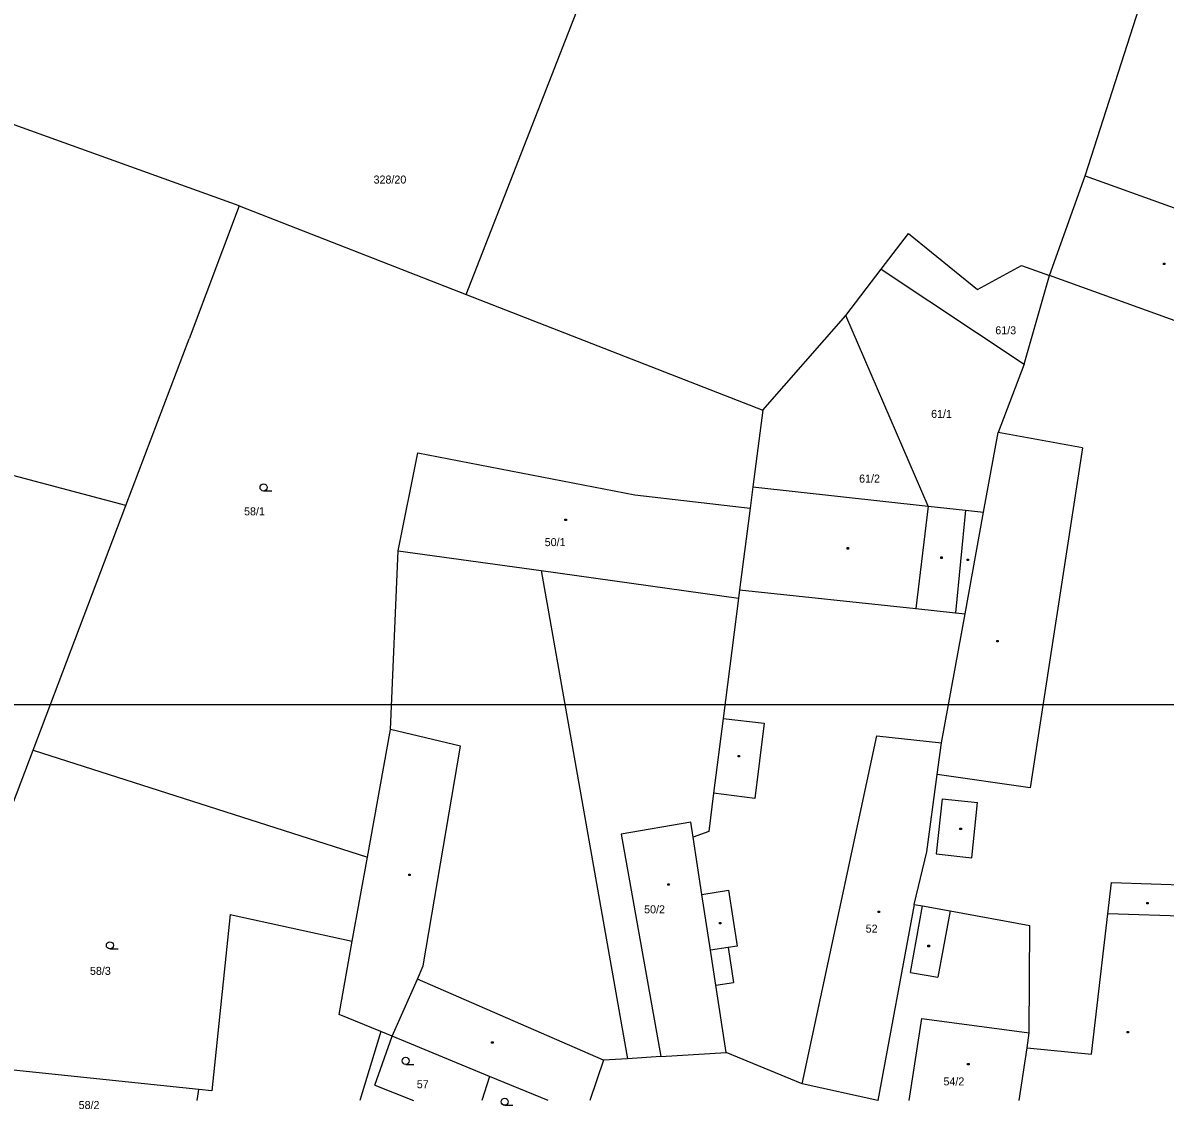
# Model space of a CAD drawing. Extents: x -770973 to -770265, y -1049936 to -1049427.
# Drawn here: x -770758.9 to -770637.6, y -1049935.7 to -1049820.3 of the extents above; entities that cross this region are included whole.
import ezdxf

# ---------------------------------------------------------------- set-up
doc = ezdxf.new("R2010")
doc.units = 0
for name, color, linetype in [('Vrstva 1', 7, 'Continuous'), ('Vrstva 14', 7, 'Continuous'), ('Vrstva 15', 7, 'Continuous'), ('Vrstva 2', 7, 'Continuous'), ('Vrstva 23', 7, 'Continuous'), ('Vrstva 25', 7, 'Continuous'), ('Vrstva 63', 7, 'Continuous')]:
    doc.layers.add(name, color=color, linetype=linetype)

msp = doc.modelspace()

# ---------------------------------------------------------------- linework, layer by layer
at = {"layer": 'Vrstva 1'}
for p, q in [((-770646.07, -1049836.54), (-770633.83, -1049798.35)), ((-770711.83, -1049849.13), (-770698.8, -1049815.74)), ((-770735.94, -1049839.73), (-770785.94, -1049821.72)), ((-770649.88, -1049847.14), (-770646.07, -1049836.54)), ((-770646.07, -1049836.54), (-770626.01, -1049843.75)), ((-770735.94, -1049839.73), (-770741.27, -1049853.85)), ((-770735.94, -1049839.73), (-770711.83, -1049849.13)), ((-770667.76, -1049846.45), (-770664.86, -1049842.66)), ((-770664.86, -1049842.66), (-770657.53, -1049848.62)), ((-770671.51, -1049851.36), (-770667.76, -1049846.45)), ((-770667.76, -1049846.45), (-770652.56, -1049856.54)), ((-770657.53, -1049848.62), (-770652.84, -1049846.08)), ((-770652.84, -1049846.08), (-770649.88, -1049847.14)), ((-770652.56, -1049856.54), (-770649.88, -1049847.14)), ((-770711.83, -1049849.13), (-770680.33, -1049861.42)), ((-770680.33, -1049861.42), (-770671.51, -1049851.36)), ((-770662.74, -1049871.61), (-770671.51, -1049851.36)), ((-770747.99, -1049871.56), (-770741.27, -1049853.85)), ((-770652.56, -1049856.54), (-770655.31, -1049863.79)), ((-770747.99, -1049871.56), (-770799.97, -1049857.75)), ((-770680.33, -1049861.42), (-770681.37, -1049869.56)), ((-770656.86, -1049872.26), (-770655.31, -1049863.79)), ((-770719.06, -1049876.36), (-770716.96, -1049865.96)), ((-770716.96, -1049865.96), (-770693.91, -1049870.43)), ((-770681.37, -1049869.56), (-770681.66, -1049871.83)), ((-770681.37, -1049869.56), (-770662.74, -1049871.61)), ((-770693.91, -1049870.43), (-770681.66, -1049871.83)), ((-770757.85, -1049897.54), (-770747.99, -1049871.56)), ((-770681.66, -1049871.83), (-770682.78, -1049880.53)), ((-770662.74, -1049871.61), (-770658.78, -1049872.05)), ((-770658.83, -1049883.07), (-770656.86, -1049872.26)), ((-770658.78, -1049872.05), (-770656.86, -1049872.26)), ((-770719.89, -1049895.36), (-770719.06, -1049876.36)), ((-770703.85, -1049878.47), (-770694.68, -1049930.32)), ((-770703.85, -1049878.47), (-770682.89, -1049881.38)), ((-770682.78, -1049880.53), (-770682.89, -1049881.38)), ((-770682.89, -1049881.38), (-770684.53, -1049894.18)), ((-770661.33, -1049896.78), (-770658.83, -1049883.07)), ((-770684.53, -1049894.18), (-770685.55, -1049902.12)), ((-770722.33, -1049908.91), (-770719.89, -1049895.36)), ((-770661.79, -1049900.14), (-770661.33, -1049896.78)), ((-770760.01, -1049903.23), (-770757.85, -1049897.54)), ((-770757.85, -1049897.54), (-770722.33, -1049908.91)), ((-770662.9, -1049908.35), (-770661.79, -1049900.14)), ((-770685.55, -1049902.12), (-770686.07, -1049906.19)), ((-770686.07, -1049906.19), (-770687.73, -1049906.77)), ((-770686.79, -1049912.86), (-770687.73, -1049906.77)), ((-770723.94, -1049917.84), (-770722.33, -1049908.91)), ((-770664.25, -1049913.92), (-770662.9, -1049908.35)), ((-770685.88, -1049918.79), (-770686.79, -1049912.86)), ((-770736.91, -1049915), (-770738.87, -1049933.74)), ((-770736.91, -1049915), (-770723.94, -1049917.84)), ((-770664.25, -1049913.92), (-770668.1, -1049934.74)), ((-770664.25, -1049913.92), (-770663.34, -1049914.09)), ((-770663.34, -1049914.09), (-770660.43, -1049914.62)), ((-770660.43, -1049914.62), (-770651.97, -1049916.16)), ((-770652.01, -1049927.55), (-770651.97, -1049916.16)), ((-770725.34, -1049925.61), (-770723.94, -1049917.84)), ((-770685.31, -1049922.52), (-770685.88, -1049918.79)), ((-770684.21, -1049929.65), (-770685.31, -1049922.52)), ((-770720.91, -1049927.44), (-770725.34, -1049925.61)), ((-770720.91, -1049927.44), (-770723.14, -1049934.76)), ((-770721.53, -1049933.14), (-770719.71, -1049927.93)), ((-770719.71, -1049927.93), (-770720.91, -1049927.44)), ((-770709.37, -1049932.19), (-770719.71, -1049927.93)), ((-770652.25, -1049929.16), (-770652.01, -1049927.55)), ((-770653.07, -1049934.76), (-770652.25, -1049929.16)), ((-770740.24, -1049933.6), (-770769.85, -1049930.5)), ((-770697.24, -1049930.48), (-770698.7, -1049934.76)), ((-770694.68, -1049930.32), (-770697.24, -1049930.48)), ((-770691.14, -1049930.09), (-770694.68, -1049930.32)), ((-770691.14, -1049930.09), (-770684.21, -1049929.65)), ((-770676.15, -1049932.97), (-770684.21, -1049929.65)), ((-770721.53, -1049933.14), (-770717.42, -1049934.76)), ((-770709.37, -1049932.19), (-770710.18, -1049934.76)), ((-770703.13, -1049934.76), (-770709.37, -1049932.19)), ((-770668.1, -1049934.74), (-770676.15, -1049932.97)), ((-770740.41, -1049934.76), (-770740.24, -1049933.6)), ((-770738.87, -1049933.74), (-770740.24, -1049933.6)), ((-770668.07, -1049934.76), (-770668.1, -1049934.74))]:
    msp.add_line(p, q, dxfattribs=at)
at = {"layer": 'Vrstva 2'}
for p, q in [((-770630.25, -1049854.2), (-770649.88, -1049847.14)), ((-770646.35, -1049865.43), (-770655.31, -1049863.79)), ((-770646.35, -1049865.43), (-770651.91, -1049901.53)), ((-770662.74, -1049871.61), (-770664.06, -1049882.51)), ((-770658.78, -1049872.05), (-770659.86, -1049882.96)), ((-770719.06, -1049876.36), (-770703.85, -1049878.47)), ((-770682.78, -1049880.53), (-770664.06, -1049882.51)), ((-770664.06, -1049882.51), (-770659.86, -1049882.96)), ((-770659.86, -1049882.96), (-770658.83, -1049883.07)), ((-770684.53, -1049894.18), (-770680.16, -1049894.67)), ((-770712.42, -1049897.11), (-770719.89, -1049895.36)), ((-770680.16, -1049894.67), (-770681.18, -1049902.68)), ((-770676.15, -1049932.97), (-770668.2, -1049896.01)), ((-770668.2, -1049896.01), (-770661.33, -1049896.78)), ((-770716.39, -1049920.44), (-770712.42, -1049897.11)), ((-770651.91, -1049901.53), (-770661.79, -1049900.14)), ((-770681.18, -1049902.68), (-770685.55, -1049902.12)), ((-770661.28, -1049902.71), (-770661.89, -1049908.57)), ((-770661.28, -1049902.71), (-770657.5, -1049903.11)), ((-770658.11, -1049908.97), (-770657.5, -1049903.11)), ((-770687.97, -1049905.19), (-770695.36, -1049906.47)), ((-770687.73, -1049906.77), (-770687.97, -1049905.19)), ((-770695.36, -1049906.47), (-770691.14, -1049930.09)), ((-770661.89, -1049908.57), (-770658.11, -1049908.97)), ((-770686.79, -1049912.86), (-770683.95, -1049912.42)), ((-770683.95, -1049912.42), (-770683.04, -1049918.35)), ((-770643.67, -1049914.92), (-770643.29, -1049911.61)), ((-770643.29, -1049911.61), (-770634.44, -1049911.9)), ((-770664.62, -1049921.14), (-770663.34, -1049914.09)), ((-770660.43, -1049914.62), (-770661.71, -1049921.67)), ((-770645.39, -1049929.82), (-770643.67, -1049914.92)), ((-770634.76, -1049915.2), (-770643.67, -1049914.92)), ((-770684, -1049918.5), (-770685.88, -1049918.79)), ((-770683.04, -1049918.35), (-770684, -1049918.5)), ((-770684, -1049918.5), (-770683.42, -1049922.23)), ((-770717.02, -1049921.86), (-770716.39, -1049920.44)), ((-770719.71, -1049927.93), (-770717.02, -1049921.86)), ((-770697.24, -1049930.48), (-770717.02, -1049921.86)), ((-770685.31, -1049922.52), (-770683.42, -1049922.23)), ((-770664.62, -1049921.14), (-770661.71, -1049921.67)), ((-770664.76, -1049934.76), (-770663.42, -1049926.03)), ((-770663.42, -1049926.03), (-770652.01, -1049927.55)), ((-770652.25, -1049929.16), (-770645.39, -1049929.82))]:
    msp.add_line(p, q, dxfattribs=at)
at = {"layer": 'Vrstva 23'}
for p, q in [((-770733.36, -1049870.01), (-770732.48, -1049870.01)), ((-770749.68, -1049918.65), (-770748.8, -1049918.65)), ((-770718.26, -1049930.92), (-770717.38, -1049930.92)), ((-770707.74, -1049935.26), (-770706.86, -1049935.26))]:
    msp.add_line(p, q, dxfattribs=at)
for centre in [(-770733.36, -1049869.64), (-770749.68, -1049918.27), (-770718.26, -1049930.54), (-770707.74, -1049934.89)]:
    msp.add_circle(centre, 0.375, dxfattribs=at)
at = {"layer": 'Vrstva 25'}
for p, q in [((-770637.77, -1049845.81), (-770637.62, -1049845.81)), ((-770637.77, -1049845.96), (-770637.77, -1049845.81)), ((-770637.62, -1049845.81), (-770637.62, -1049845.96)), ((-770637.62, -1049845.96), (-770637.77, -1049845.96)), ((-770701.34, -1049872.99), (-770701.19, -1049872.99)), ((-770701.34, -1049873.14), (-770701.34, -1049872.99)), ((-770701.19, -1049873.14), (-770701.34, -1049873.14)), ((-770701.19, -1049872.99), (-770701.19, -1049873.14)), ((-770671.37, -1049876.03), (-770671.22, -1049876.03)), ((-770671.37, -1049876.18), (-770671.37, -1049876.03)), ((-770671.22, -1049876.18), (-770671.37, -1049876.18)), ((-770671.22, -1049876.03), (-770671.22, -1049876.18)), ((-770661.4, -1049877.02), (-770661.25, -1049877.02)), ((-770661.4, -1049877.17), (-770661.4, -1049877.02)), ((-770661.25, -1049877.17), (-770661.4, -1049877.17)), ((-770661.25, -1049877.02), (-770661.25, -1049877.17)), ((-770658.61, -1049877.26), (-770658.46, -1049877.26)), ((-770658.61, -1049877.41), (-770658.61, -1049877.26)), ((-770658.46, -1049877.26), (-770658.46, -1049877.41)), ((-770658.46, -1049877.41), (-770658.61, -1049877.41)), ((-770655.47, -1049885.9), (-770655.32, -1049885.9)), ((-770655.47, -1049886.05), (-770655.47, -1049885.9)), ((-770655.32, -1049886.05), (-770655.47, -1049886.05)), ((-770655.32, -1049885.9), (-770655.32, -1049886.05)), ((-770682.94, -1049898.11), (-770682.79, -1049898.11)), ((-770682.94, -1049898.26), (-770682.94, -1049898.11)), ((-770682.79, -1049898.26), (-770682.94, -1049898.26)), ((-770682.79, -1049898.11), (-770682.79, -1049898.26)), ((-770659.38, -1049905.82), (-770659.23, -1049905.82)), ((-770659.38, -1049905.97), (-770659.38, -1049905.82)), ((-770659.23, -1049905.97), (-770659.38, -1049905.97)), ((-770659.23, -1049905.82), (-770659.23, -1049905.97)), ((-770717.92, -1049910.72), (-770717.77, -1049910.72)), ((-770717.92, -1049910.87), (-770717.92, -1049910.72)), ((-770717.77, -1049910.87), (-770717.92, -1049910.87)), ((-770717.77, -1049910.72), (-770717.77, -1049910.87)), ((-770690.42, -1049911.73), (-770690.27, -1049911.73)), ((-770690.42, -1049911.88), (-770690.42, -1049911.73)), ((-770690.27, -1049911.88), (-770690.42, -1049911.88)), ((-770690.27, -1049911.73), (-770690.27, -1049911.88)), ((-770639.54, -1049913.72), (-770639.39, -1049913.72)), ((-770639.54, -1049913.87), (-770639.54, -1049913.72)), ((-770639.39, -1049913.72), (-770639.39, -1049913.87)), ((-770668.08, -1049914.65), (-770667.93, -1049914.65)), ((-770668.08, -1049914.8), (-770668.08, -1049914.65)), ((-770667.93, -1049914.8), (-770668.08, -1049914.8)), ((-770667.93, -1049914.65), (-770667.93, -1049914.8)), ((-770639.39, -1049913.87), (-770639.54, -1049913.87)), ((-770684.92, -1049915.83), (-770684.77, -1049915.83)), ((-770684.92, -1049915.98), (-770684.92, -1049915.83)), ((-770684.77, -1049915.98), (-770684.92, -1049915.98)), ((-770684.77, -1049915.83), (-770684.77, -1049915.98)), ((-770662.78, -1049918.27), (-770662.63, -1049918.27)), ((-770662.78, -1049918.42), (-770662.78, -1049918.27)), ((-770662.63, -1049918.42), (-770662.78, -1049918.42)), ((-770662.63, -1049918.27), (-770662.63, -1049918.42)), ((-770641.63, -1049927.41), (-770641.48, -1049927.41)), ((-770641.63, -1049927.56), (-770641.63, -1049927.41)), ((-770641.48, -1049927.56), (-770641.63, -1049927.56)), ((-770641.48, -1049927.41), (-770641.48, -1049927.56)), ((-770709.13, -1049928.52), (-770708.98, -1049928.52)), ((-770709.13, -1049928.67), (-770709.13, -1049928.52)), ((-770708.98, -1049928.67), (-770709.13, -1049928.67)), ((-770708.98, -1049928.52), (-770708.98, -1049928.67)), ((-770658.56, -1049930.82), (-770658.41, -1049930.82)), ((-770658.56, -1049930.97), (-770658.56, -1049930.82)), ((-770658.41, -1049930.97), (-770658.56, -1049930.97)), ((-770658.41, -1049930.82), (-770658.41, -1049930.97))]:
    msp.add_line(p, q, dxfattribs=at)
at = {"layer": 'Vrstva 63'}
msp.add_lwpolyline([(-770858.67, -1049892.7), (-770264.67, -1049892.7), (-770264.67, -1049472.7), (-770858.67, -1049472.7), (-770858.67, -1049892.7)], dxfattribs=at)

# ---------------------------------------------------------------- texts
at = {"layer": 'Vrstva 14'}
for s, p in [('328/20', (-770721.67, -1049837.36)), ('61/3', (-770655.62, -1049853.37)), ('61/1', (-770662.44, -1049862.25)), ('61/2', (-770670.09, -1049869.12)), ('58/1', (-770735.43, -1049872.6)), ('58/3', (-770751.8, -1049921.41)), ('57', (-770717.08, -1049933.45)), ('58/2', (-770753, -1049935.66))]:
    msp.add_text(s, height=0.85, dxfattribs=at).set_placement(p)
at = {"layer": 'Vrstva 15'}
for s, p in [('50/1', (-770703.49, -1049875.87)), ('50/2', (-770692.93, -1049914.87)), ('52', (-770669.39, -1049916.92)), ('54/2', (-770661.13, -1049933.15))]:
    msp.add_text(s, height=0.85, dxfattribs=at).set_placement(p)

doc.saveas('drawing.dxf')
